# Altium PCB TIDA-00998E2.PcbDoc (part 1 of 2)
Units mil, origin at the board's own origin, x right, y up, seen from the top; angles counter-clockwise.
Board outline 2559.06 x 2559.06 mil, 2 copper layers (Top Layer, Bottom Layer), stack 62 mil thick; 110 components, 76 nets, 294 pads, 121 vias.
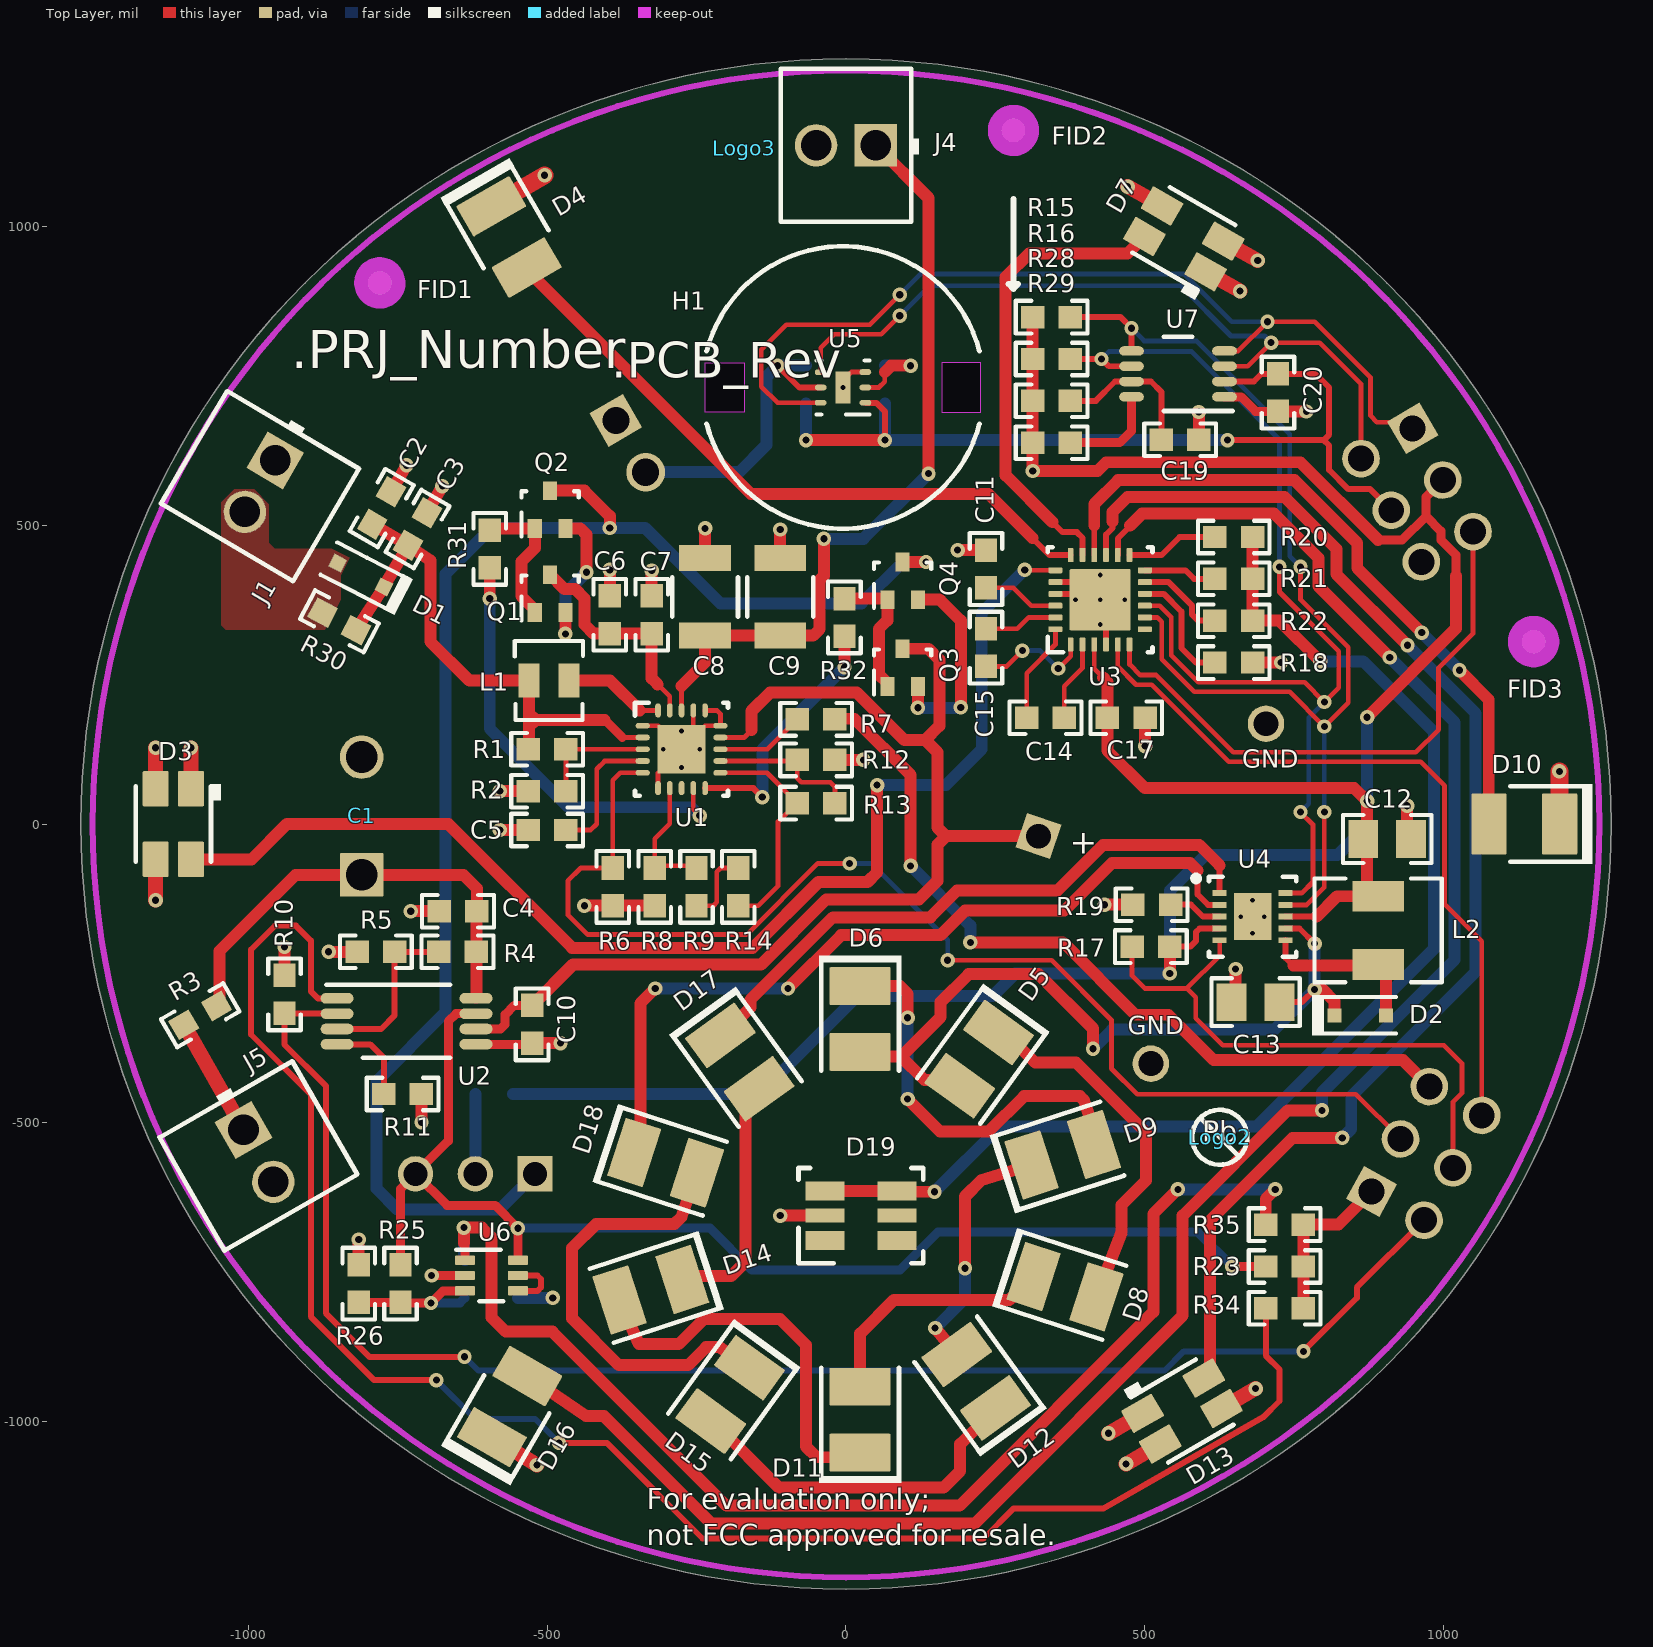
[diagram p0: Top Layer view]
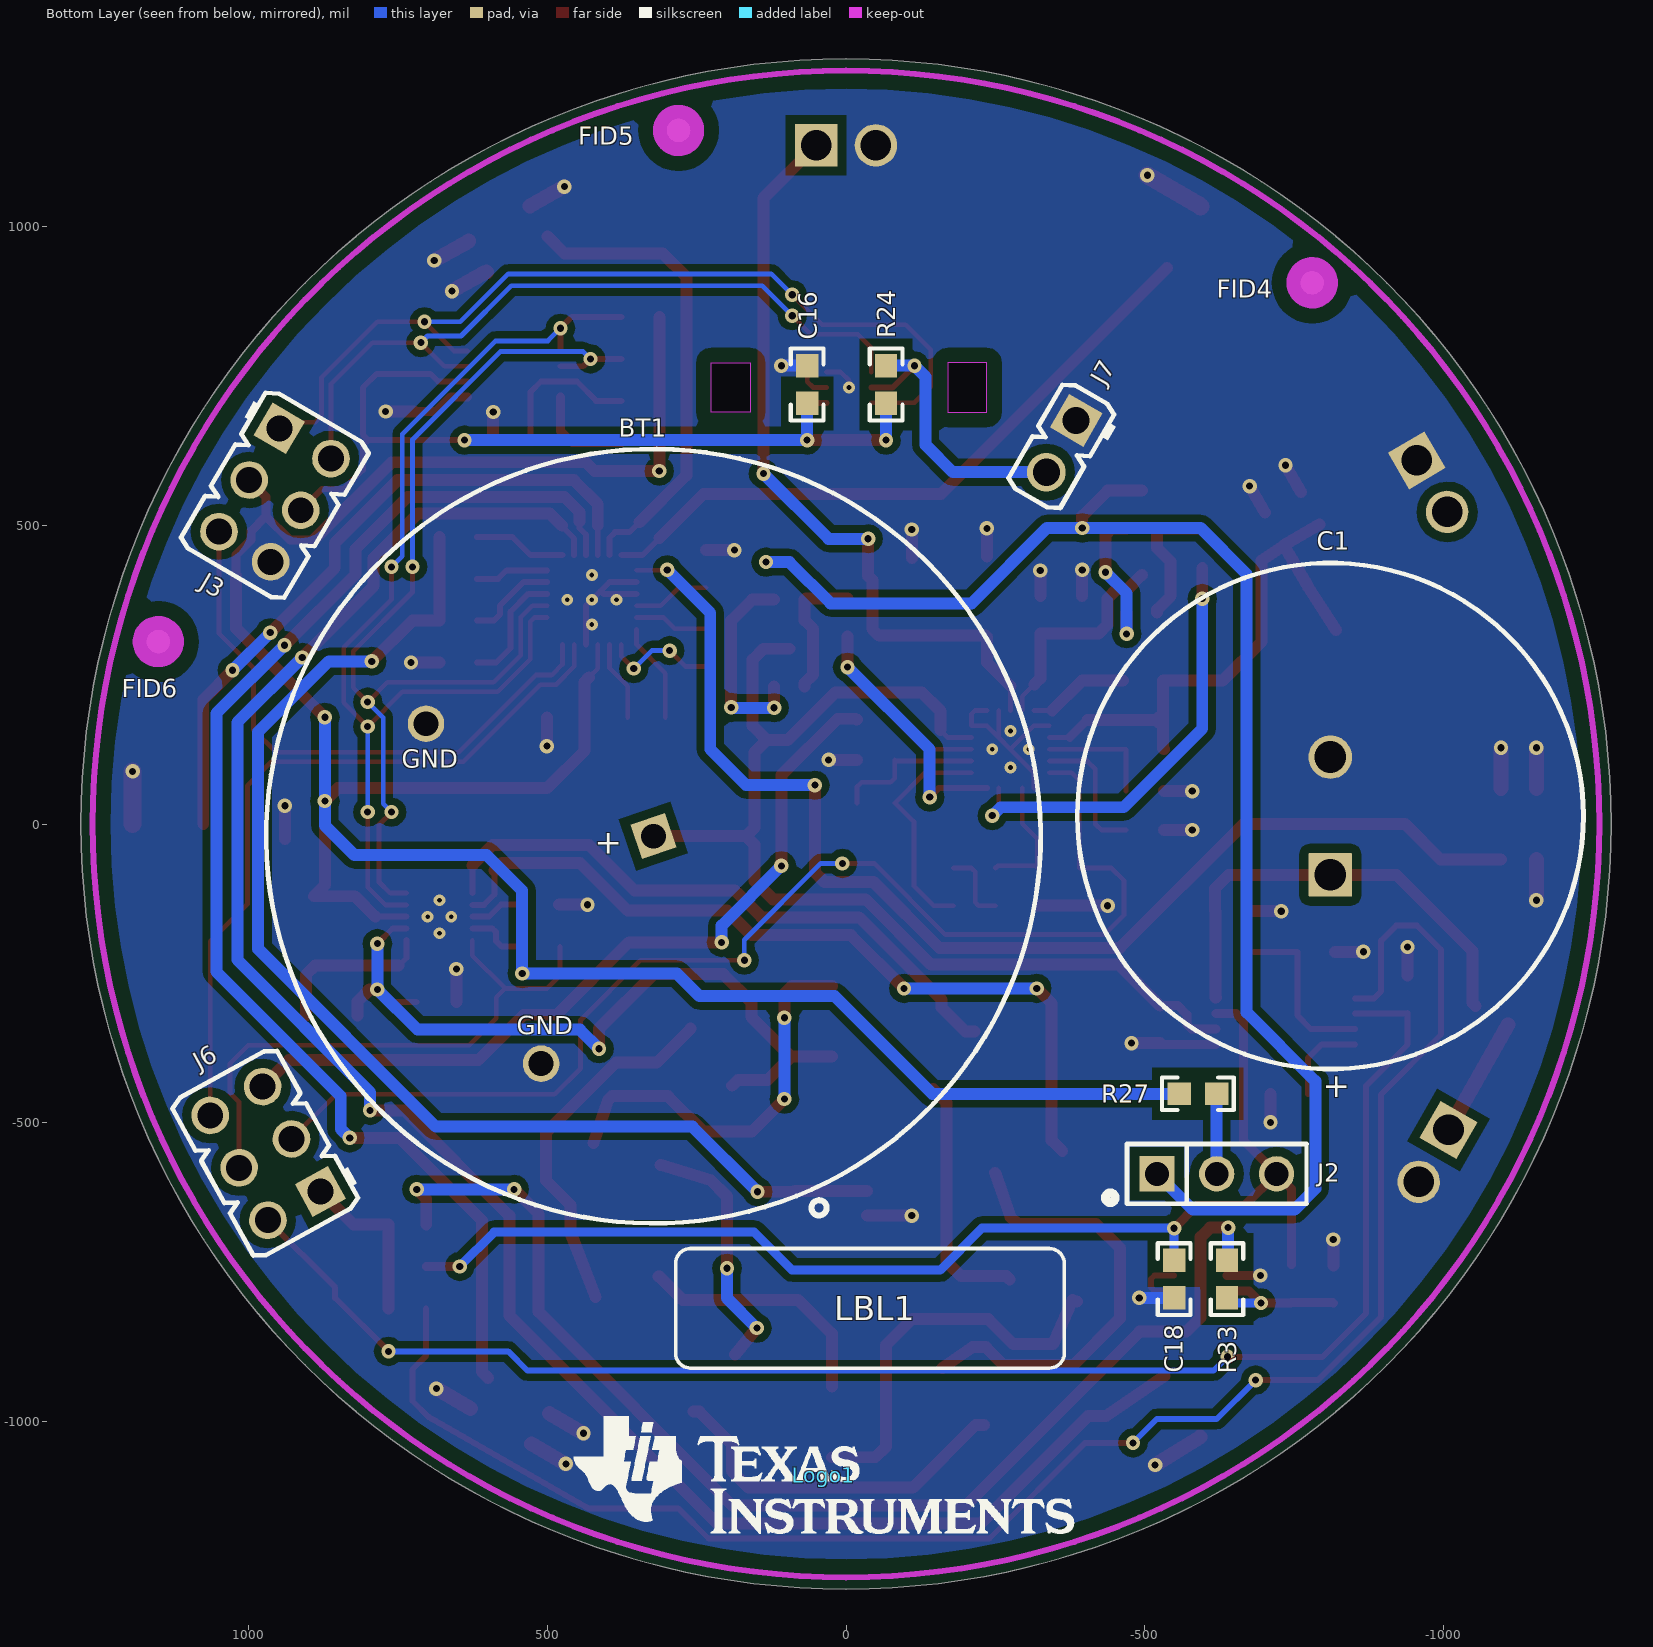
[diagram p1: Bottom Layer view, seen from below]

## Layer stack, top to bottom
Top Solder: solder mask 0.4, Solder Resist, Dk 3.5
Top Layer: signal copper 1.4
Dielectric1: core 59.2, FR-4 High Tg, Dk 4.8
Bottom Layer: signal copper 1.4
Bottom Solder: solder mask 0.4, Solder Resist, Dk 3.5

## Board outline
0,-1279.53 cw(c0,0) -1279.53,0 cw(c0,0) 0,1279.53 cw(c0,0) 1279.53,0 cw(c0,0)

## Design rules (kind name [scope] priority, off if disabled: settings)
AcuteAngle [All] p1: minimum=4.50000000000000E+0001 checktracksonly=FALSE
AssemblyTestPointUsage [All] p1: valid=2
Clearance Clearance_Keepouts [((IsTrack Or IsArc) And Not InPoly) And IsFree and IsKeepOut vs ((IsTrack Or IsArc) And Not InPoly) And IsFree and IsKeepOut] p1: gap=0
Clearance Clearance_Poly [InPolygon] p2: gap=25 except(12: Track-Poly Via-Poly; 15: THPad-Poly)
Clearance [All] p3: gap=7.87 except(8: Track-Track)
ComponentClearance ComponentClearance_MountingHoles_FiducialMarks [InComponentClass('Mounting Holes') vs InComponentClass('FiducialMark')] p1: gap=50 collisioncheckmode=3 verticalgap=10 showdistances=FALSE
ComponentClearance ComponentClearance_Shunt [InComponentClass('Header') vs InComponentClass('Shunt')] p2: gap=0 collisioncheckmode=3 verticalgap=0 showdistances=FALSE
ComponentClearance ComponentClearance_Logo [InComponentClass('Logo')] p3: gap=50 collisioncheckmode=3 verticalgap=10 showdistances=FALSE
ComponentClearance ComponentClearance_ScrewToNut [(HasFootprint('NY PMS 440 0025 PH')) vs (HasFootprint('Keystone_1902C'))] p4: gap=5 collisioncheckmode=3 verticalgap=10 showdistances=FALSE
ComponentClearance ComponentClearance_MountingHoles [InComponentClass('Mounting Holes')] p5: gap=250 collisioncheckmode=3 verticalgap=100000 showdistances=FALSE
ComponentClearance ComponentClearance_SmallPassives [HasFootprint('0201*') or HasFootprint('0402*') or HasFootprint('0508') or HasFootprint('0603*') or HasFootprint('0612') or HasFootprint('0805*') or HasFootprint('0815*') or HasFootprint('0830*') or HasFootprint('1206*') or HasFootprint('1210*') or HasFootprint('1808*') or HasFootprint('1812*') or HasFootprint('1825*') or HasFootprint('2010*') or HasFootprint('2220*') or HasFootprint('2225*') or HasFootprint('2512*') or HasFootprint('2728*') or HasFootprint('3518*') vs HasFootprint('0201*') or HasFootprint('0402*') or HasFootprint('0508') or HasFootprint('0603*') or HasFootprint('0612') or HasFootprint('0805*') or HasFootprint('0815*') or HasFootprint('0830*') or HasFootprint('1206*') or HasFootprint('1210*') or HasFootprint('1808*') or HasFootprint('1812*') or HasFootprint('1825*') or HasFootprint('2010*') or HasFootprint('2220*') or HasFootprint('2225*') or HasFootprint('2512*') or HasFootprint('2728*') or HasFootprint('3518*')] p6: gap=14.96 collisioncheckmode=3 verticalgap=10 showdistances=FALSE
ComponentClearance ComponentClearance_THtoSMT [IsThruComponent vs IsSMTComponent] p7: gap=40 collisioncheckmode=3 verticalgap=30 showdistances=FALSE
ComponentClearance ComponentClearance_THtoTH [IsThruComponent vs IsThruComponent] p8: gap=25 collisioncheckmode=3 verticalgap=30 showdistances=FALSE
ComponentClearance [All] p9: gap=30 collisioncheckmode=3 verticalgap=10 showdistances=FALSE
DiffPairsRouting [All] p1: maxlimit=100 minlimit=10 mostfreqgap=10 toplayer_minwidth=15 toplayer_maxwidth=15 toplayer_prefwidth=15 bottomlayer_minwidth=15 bottomlayer_maxwidth=15 bottomlayer_prefwidth=15 maxuncoupledlength=1000
FabricationTestPointUsage TestPointUsage [All] p1: valid=2 allowmultiple=FALSE
FabricationTestpoint Testpoint [All] p1: side=3 testpointundercomponent=TRUE minsize=40 maxsize=100 preferedsize=60 minholesize=0 maxholesize=40 preferedholesize=32 testpointgrid=1 allowsidetop=TRUE allowsidebottom=TRUE usegrid=TRUE gridtolerance=0.01
FanoutControl Fanout_LCC [IsLCC] p1: bgadir=Out bgaviamode=Centered fanoutstyle=Auto fanoutdirection=Alternating viagrid=1 // Fanout_LCC (Default Rule)
FanoutControl Fanout_BGA [IsBGA] p2: bgadir=Out bgaviamode=Centered fanoutstyle=Auto fanoutdirection=Alternating viagrid=1 // Fanout_BGA (Default Rule)
FanoutControl Fanout_Default [All] p4: bgadir=Out bgaviamode=Centered fanoutstyle=Auto fanoutdirection=Alternating viagrid=1 // Fanout_Default (Default Rule)
FanoutControl Fanout_Small [(CompPinCount < 5)] p5: bgadir=Out bgaviamode=Centered fanoutstyle=Auto fanoutdirection=OutThenIn viagrid=1 // Fanout_Small (Default Rule)
HoleSize [All] p1: absolutevalues=TRUE maxlimit=251 minlimit=7.87 maxpercent=80.000 minpercent=20.000
MinimumAnnularRing MinimumAnnularRing_ThermalPadVias [IsVia and InAnyComponent] p1: minimumring=5.91
MinimumAnnularRing [All] p2: minimumring=6
MinimumSolderMaskSliver MinimumSolderMaskSliver_Logo [InComponentClass('Logo') vs InComponentClass('Logo')] p1: minsoldermaskwidth=0.7
MinimumSolderMaskSliver [All] p2: minsoldermaskwidth=3.94
PlaneConnect [All] p1: planeconnectstyle=Relief reliefexpansion=10 reliefentries=4 reliefconductorwidth=10 reliefairgap=10
PolygonConnect PolygonConnect_Via [IsVia] p1: connectstyle=Direct reliefconductorwidth=10 reliefentries=4 polygonreliefangle="90 Angle" airgapwidth=10
PolygonConnect PolygonConnect_1 [All] p2: connectstyle=Direct reliefconductorwidth=15 reliefentries=4 polygonreliefangle="90 Angle" airgapwidth=10
RoutingVias ThermalPadVias [IsVia and InAnyComponent] p1: holewidth=7.87 width=19.68 viastyle="Through Hole" minholewidth=7.87 minwidth=19.68 maxholewidth=12.99 maxwidth=23.62
RoutingVias [All] p2: holewidth=12 width=24 viastyle="Through Hole" minholewidth=12 minwidth=24 maxholewidth=20 maxwidth=40
SilkToBoardRegionClearance [Not ((IsComment or IsDesignator) And (Hide <> 'False')) and not InRegion(1000,500,4000,800)] p1:
SilkToSilkClearance SilkToSilkClearance_Pb-FreeLogo [(HasFootprint('Pb-Free_Overlay_Medium') OR HasFootprint('Pb-Free_Overlay_Small')) vs (HasFootprint('Pb-Free_Overlay_Medium') OR HasFootprint('Pb-Free_Overlay_Small'))] p1: silktosilkclearance=0
SilkToSilkClearance [All] p2: silktosilkclearance=2
SilkToSolderMaskClearance SilkToComponentPadClearance [IsPad and InAnycomponent] p1: minsilkscreentomaskgap=5 clearancetoexposedcopper=TRUE
SilkToSolderMaskClearance "Silk to Solder Mask Opening" [All] p2: minsilkscreentomaskgap=4 clearancetoexposedcopper=FALSE
SolderMaskExpansion [All] p1: expansion=2
Width [All] p1: maxlimit=100 minlimit=6 preferedwidth=8 checkconnectedcopper=TRUE
15 further rules are at their usual default settings.

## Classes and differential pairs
component class Header: J2 J3 J6 J7
component class TIDA-00998E2_EVM_Hardware: FID1 FID2 FID3 FID4 FID5 FID6 H1 LBL1 Logo1 Logo2 Logo3 ZZ1 ZZ2 ZZ3 ZZ4
component class FiducialMark: FID1 FID2 FID3 FID4 FID5 FID6
component class AssemblyNote: ZZ1 ZZ2 ZZ3 ZZ4
component class Label: LBL1
component class Logo: Logo1
component class TIDA-00998E2_BlankSheet: BT1 C1 C2 C3 C4 C5 C6 C7 C8 C9 C10 C11 C12 C13 C14 C15 C16 C17 C18 C19 C20 D1 D2 D3 D4 D5 D6 D7 D8 D9 D10 D11 D12 D13 D14 D15 D16 D17 D18 D19 J1 J2 J3 J4 J5 J6 J7 L1 L2 Q1 Q2 Q3 Q4 R1 R2 R3 R4 R5 R6 R7 R8 R9 R10 R11 R12 R13 R14 R15 R16 R17 R18 R19 R20 R21 R22 R23 R24 R25 R26 R27 R28 R29 R30 R31 R32 R33 R34 R35 U1 U2 U3 U4 U5 U6 U7

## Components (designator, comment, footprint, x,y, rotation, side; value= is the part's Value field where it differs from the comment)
BT1 "TL-4934/P" Tadiran_TL-4934 322.04,-20.32 r251.3 bottom locked
C1 "DB-5R5D105T" DB_2150x800 -810,13.43 r90 top locked
C2 "0603ZD475KAT2A" 0603 -776.56,528.32 r60 top
C3 "06033C104JAT2A" 0603 -716.56,493.32 r60 top
C4 "06033C104JAT2A" 0603 -648.91,-145.8 r180 top
C5 "C0603C103J5RACTU" 0603 -500,-10 r180 top
C6 "0603ZD475KAT2A" 0603 -395,350 r90 top
C7 "06033C104JAT2A" 0603 -325,350 r90 top
C8 "C1210C107M8PACTU" 1210_280 -235.63,380 r90 top
C9 "C1210C107M8PACTU" 1210_280 -110,380 r90 top
C10 "06033C104JAT2A" 0603 -525,-335 r270 top
C11 "C0603C105K8PACTU" 0603 234.14,426.48 r90 top
C12 "GRM219R61E225KA12D" 0805_HV 905,-25 r180 top
C13 "GRM219R61E225KA12D" 0805_HV 685,-297.94 r0 top
C14 "C0603C474K8PACTU" 0603 333.68,177.8 r180 top
C15 "C0603C474K8PACTU" 0603 234.14,294.98 r90 top
C16 "06033C104JAT2A" 0603 65,735 r90 bottom
C17 "06033C104JAT2A" 0603 468.68,177.73 r0 top
C18 "06033C104JAT2A" 0603 -548.68,-761 r270 bottom
C19 "06033C104JAT2A" 0603 558.76,642.75 r0 top
C20 "06033C104JAT2A" 0603 722.5,721.45 r270 top
D1 "1SS315TPH3F" SOD-323 -811.4,416.43 r152.75 top
D2 "1N4448WX-TP" SOD-323 860,-320 r0 top
D3 "HSMZ-A400-V30M1" HSMx-A4xx_Red -1125,0 r180 top
D4 "VAOL-S2WR4" VAOL-S2WR4_Yellow -563.64,981.86 r120 top
D5 "VLMR334BACB-GS08" VLMR334_Red#1 222.69,-393.19 r54 top
D6 "VLMR334BACB-GS08" VLMR334_Red#1 23.59,-326.06 r90 top
D7 "HSMZ-A400-V30M1" HSMx-A4xx_Red 565,978.61 r60 top
D8 "VLMR334BACB-GS08" VLMR334_Red#1 366.26,-773.78 r162 top
D9 "VLMR334BACB-GS08" VLMR334_Red#1 362.42,-552.97 r198 top
D10 "VAOL-S2WR4" VAOL-S2WR4_Yellow 1134.49,0 r0 top
D11 "VLMR334BACB-GS08" VLMR334_Red#1 23.59,-996.06 r270 top
D12 "VLMR334BACB-GS08" VLMR334_Red#2 137.51,-921.94 r126 top
D13 "HSMZ-A400-V30M1" HSMx-A4xx_Red 562.03,-981.64 r300 top
D14 "VLMR334BACB-GS08" VLMR334_Red#1 -326.26,-778.78 r18 top
D15 "VLMR334BACB-GS08" VLMR334_Red#3 -189.2,-947.56 r54 top
D16 "VAOL-S2WR4" VAOL-S2WR4_Yellow -562.5,-974.28 r240 top
D17 "VLMR334BACB-GS08" VLMR334_Red#1 -177.69,-398.19 r126 top
D18 "VLMR334BACB-GS08" VLMR334_Red#1 -301.77,-566.22 r162 top
D19 "LNJ8L6C18RA" LNJ8L6C18RA_Red 25,-655 r90 top
FID1 "Fiducial" Fiducial10-20 -779.68,905 r20.33 top
FID2 "Fiducial" Fiducial10-20 280,1160 r0 top
FID3 "Fiducial" Fiducial10-20 1150,305 r169.88 top
FID4 "Fiducial" Fiducial10-20 -779.68,905 r90 bottom
FID5 "Fiducial" Fiducial10-20 280,1160 r90 bottom
FID6 "Fiducial" Fiducial10-20 1150,305 r90 bottom
H1 "IML-0669" Murata_IML-0669 -5,730 r0 top locked
J1 "OSTVN02A150" On-Shore_OSTVN02A150 -980,565 r239.51 top
J2 "PEC03SAAN" CONN_PEC03SAAN -620,-585 r180 bottom
J3 "61300621121" Wurth_61300621121 955,550 r210.31 bottom
J4 "OSTVN02A150" On-Shore_OSTVN02A150 0,1135 r180 top
J5 "OSTVN02A150" On-Shore_OSTVN02A150 -982.75,-555 r299.86 top
J6 "61300621121" Wurth_61300621121 971.2,-550.88 r331.15 bottom
J7 "61300211121" WURTH_61300211121 -360,631.6 r300 bottom
L1 "VLF302515MT-100M" VLF302515MT -496.79,240 r0 top
L2 "VLF504012MT-100M" VLF504012MT 890,-177.91 r270 top
LBL1 "Size: 0.65\" x 0.20 \"" Label_650x200 -40,-810 r180 bottom
Logo1 "Texas Instruments" TI_Stacked_Overlay_Small 37,-1089 r180 bottom
Logo2 "Pb-Free Symbol" Pb-Free_Overlay_Small 625,-524 r0 top
Logo3 "FCC disclaimer" FCC_disclaimer -170,1130 r0 top
Q1 "SI1317DL-T1-GE3" SOT-323 -494.88,385.27 r90 top
Q2 "SI1317DL-T1-GE3" SOT-323 -494.88,525.93 r90 top
Q3 "SI1317DL-T1-GE3" SOT-323 94.68,261.57 r90 top
Q4 "SI1317DL-T1-GE3" SOT-323 94.68,406.57 r90 top
R1 "RC0603JR-070RL" 0603 -500,125 r0 top
R2 "CRCW0603100KFKEA" 0603 -500,55 r180 top
R3 "RC0603JR-070RL" 0603 -1080,-320 r30 top
R4 "CRCW06033M48FKEA" 0603 -649.7,-213.74 r0 top
R5 "CRCW06031M00FKEA" 0603 -786.2,-213.74 r0 top
R6 "RC0603JR-070RL" 0603 -390,-105.08 r90 top
R7 "RC0603JR-070RL" 0603 -50,175 r180 top
R8 "CRCW06035M49FKEA" 0603 -320,-105.08 r90 top
R9 "CRCW06037M32FKEA" 0603 -250,-105.08 r270 top
R10 "RC0603JR-070RL" 0603 -939.05,-284.8 r270 top
R11 "CRCW0603499RFKEA" 0603 -741.5,-451.56 r180 top
R12 "CRCW06034M32FKEA" 0603 -50,107.24 r180 top
R13 "CRCW06037M50FKEA" 0603 -50,35 r180 top
R14 "CRCW06031M18FKEA" 0603 -180,-105.08 r90 top
R15 "CRCW060310K0FKEA" 0603 343.76,847.75 r180 top
R16 "CRCW060310K0FKEA" 0603 343.76,777.75 r180 top
R17 "CRCW060310K0FKEA" 0603 510,-205 r0 top
R18 "RC0603JR-070RL" 0603 648.5,270 r180 top
R19 "CRCW06038K06FKEA" 0603 511.26,-135 r0 top
R20 "RC0603JR-070RL" 0603 648.5,480 r0 top
R21 "RC0603JR-070RL" 0603 648.5,410 r0 top
R22 "RC0603JR-070RL" 0603 648.5,340 r0 top
R23 "CRCW060310K0FKEA" 0603 733.5,-740 r180 top
R24 "CRCW060310K0FKEA" 0603 -67,735 r270 bottom
R25 "CRCW06031M80FKEA" 0603 -745,-768.5 r90 top
R26 "CRCW06031M00FKEA" 0603 -815,-768.5 r270 top
R27 "RC0603JR-070RL" 0603 -588.5,-451.31 r180 bottom
R28 "RC0603FR-07200KL" 0603 343.76,707.75 r180 top
R29 "RC0603FR-07200KL" 0603 343.76,637.75 r180 top
R30 "RC0603JR-070RL" 0603 -847.3,338.95 r332.38 top
R31 "RC0603JR-070RL" 0603 -595.78,460 r90 top
R32 "RC0603JR-070RL" 0603 -2.59,345.41 r90 top
R33 "CRCW060352K3FKEA" 0603 -637.27,-761 r90 bottom
R34 "RC0603JR-070RL" 0603 733.5,-810 r0 top
R35 "RC0603JR-070RL" 0603 733.5,-670 r0 top
U1 "BQ25505RGRR" RGR0020A -275,125 r0 top
U2 "TPS2113APWR" PW0008A_N -735,-330 r0 top
U3 "LP55231SQX/NOPB" RTW0024A 425,375 r90 top
U4 "LM3509SD/NOPB" SDA10A 680,-155 r0 top
U5 "OPT3001DNPR" DNP0006A -5,730 r180 top
U6 "TLV3011AIDCKR" DCK0006A_N -592.97,-755.09 r0 top
U7 "PCA9306DCTR" DCT0008A_N 555.26,752.75 r180 top
ZZ1 "This Assembly Note is for PCB labels only" AssemblyNoteLabel -1857,1881 r0 top
ZZ2 "These assemblies are ESD sensitive, ESD precautions shall be observed." AssemblyNote -1857,1772.11 r0 top
ZZ3 "These assemblies must be clean and free from flux and all contaminants. Use of no clean flux is not acceptable." AssemblyNote -1857,1683.56 r0 top
ZZ4 "These assemblies must comply with workmanship standards IPC-A-610 Class 2, unless otherwise specified." AssemblyNote -1857,1595 r0 top

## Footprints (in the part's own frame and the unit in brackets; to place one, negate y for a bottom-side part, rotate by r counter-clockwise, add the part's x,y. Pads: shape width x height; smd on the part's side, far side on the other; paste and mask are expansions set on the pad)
0603 [mm] "0603 from SM-752 data"
  rect 1x0.95 smd: 1(-0.8,0) 2(0.8,0)
  silkscreen extent -1.52,-0.69 1.52,0.69, body extent -0.87,-0.47 0.87,0.47, height 1
0805_HV [mil] "0805 with 30mil clearance between pads"
  rect 50x63 smd: 1(-40,0) 2(40,0)
  silkscreen extent -74,-40 74,40, body extent -43,-29 43,29, height 57
1210_280 [mm] "SMD, 2-Leads, Body 3.6x2.8mm, Height 2.8mm"
  rect 1.1x2.2 smd: 1(-1.65,0) 2(1.65,0)
  silkscreen extent -0.84,-1.4 0.84,1.4, body extent -1.8,-1.4 1.8,1.4, height 2.8
AssemblyNote [mil] "Assembly Note"
AssemblyNoteLabel [mil] "Assembly Note for PCB Labels"
CONN_PEC03SAAN [mm] "SULLINS"
  rect 1.5x1.5 hole 1.016: 1(-2.54,0)
  round 1.5 hole 1.016: 2(0,0) 3(2.54,0)
  silkscreen extent -4.72,-1.27 3.81,1.27, body extent -3.84,-1.3 3.84,1.3, height 8.38
DB_2150x800 [mm] "TH, 2-Leads, Dia 21.5mm, Pin Spacing 5mm"
  rrect5% 1.85x1.85 hole 1.35: 1(-2.5,0)
  round 1.85 hole 1.35: 2(2.5,0)
  body extent -10.75,-10.75 10.76,10.75, height 12.51
DCK0006A_N [mm] "SOT23, 6-Leads, Body 2x1.3mm, Pitch 0.65mm, Lead Span 2.1mm, IPC Medium Density"
  rrect25% 0.85x0.4 smd: 1(-1.125,0.65) 2(-1.125,0) 3(-1.125,-0.65) 4(1.125,-0.65) 5(1.125,0) 6(1.125,0.65)
  silkscreen extent -1.5,-1.09 0.51,1.09, body extent -1.14,-1 1.14,1, height 0.95
DCT0008A_N [mm] "TSOP, 8-Leads, Body 3x2.8mm, Pitch 0.65mm, IPC Medium Density"
  oval 1.05x0.4 smd: 1(-1.975,0.975) 2(-1.975,0.325) 3(-1.975,-0.325) 4(-1.975,-0.975) 5(1.975,-0.975) 6(1.975,-0.325) 7(1.975,0.325) 8(1.975,0.975)
  silkscreen extent -2.32,-1.57 0.6,1.58, body extent -2.01,-1.47 2.01,1.48, height 1.3
DNP0006A [mm] "DFN-6 2x2mm"
  oval 0.5x0.25 smd: 1(-0.95,0.65) 2(-0.95,0) 3(-0.95,-0.655) 4(0.95,-0.65) 5(0.95,0) 6(0.95,0.65)
  rect 0.65x1.35 smd paste-0.5: 7(0,0)
  silkscreen extent -1.12,-1.15 1.12,1.15, body extent -1,-1 1,1, height 0.64
FCC_disclaimer [mil]
Fiducial10-20 [mm]
  round 1 smd mask+0.5: 1(0,0)
  Top Layer keep-out lines w1.178: 0.5,0.006 ccw(c0,0) 0.5,0.006
HSMx-A4xx_Red [mm] "SMD, 4-Leads, Body 3.2x2.8mm"
  rrect9% 1.1x1.5 smd: 1(-0.75,1.5) 2(-0.75,-1.5) 2(0.75,1.5) 2(0.75,-1.5)
  silkscreen extent -2.03,-1.7 1.6,1.6, body extent -1.5,-1.85 1.5,1.85, height 2.1
Label_650x200 [mil] "Thermal Transfer Label"
  silkscreen extent -325,-100 325,100, body extent -325,-100 325,100, height 1
LNJ8L6C18RA_Red [mm] "SMT, 6-Leads, Body 3.3x3.1mm, Pitch 1.05mm"
  rect 0.8x1.65 smd: 1(-1.05,1.525) 3(1.05,1.525) 4(1.05,-1.525) 6(-1.05,-1.525)
  rect 0.6x1.65 smd: 2(0,1.525) 5(0,-1.525)
  silkscreen extent -2.03,-2.65 2.03,2.65, body extent -1.73,-1.82 1.72,1.83, height 1.95
Murata_IML-0669 [mil] "Pyroelectric Infrared Lens, TH"
  Keep-Out Layer board cut-out: -165.35,-41.34 -230.32,-41.34 -230.32,41.34 -165.35,41.34
  Keep-Out Layer board cut-out: 165.35,-41.34 230.32,-41.34 230.32,41.34 165.35,41.34
  silkscreen extent -228,-236 228,236, body extent -256,-236 256,236, height 335
On-Shore_OSTVN02A150 [mm] "Terminal Block, 2.54mm, 2-pole, Brass, TH"
  rect 1.8x1.8 hole 1.3: 1(-1.27,0)
  round 1.8 hole 1.3: 2(1.27,0)
  silkscreen extent -3.1,-3.25 2.77,3.25, body extent -2.77,-3.25 2.77,3.25, height 8.51
Pb-Free_Overlay_Small [mil]
  silkscreen extent -46,-46 46,46
PW0008A_N [mm] "TSOP, 8-Leads, Body 3x4.4mm, Pitch 0.65mm, IPC Medium Density"
  oval 1.4x0.45 smd: 1(-2.95,0.975) 2(-2.95,0.325) 3(-2.95,-0.325) 4(-2.95,-0.975) 5(2.95,-0.975) 6(2.95,-0.325) 7(2.95,0.325) 8(2.95,0.975)
  silkscreen extent -3.4,-1.55 1.85,1.55, body extent -3.21,-1.5 3.21,1.5, height 1.2
RGR0020A [mm] "QFN, 20-Leads, Body 3.5x3.5mm, Pitch 0.5mm, Thermal Pad 2.05x2.05mm, TI Recommended"
  oval 0.6x0.24 smd: 1(-1.65,1) 2(-1.65,0.5) 3(-1.65,0) 4(-1.65,-0.5) 5(-1.65,-1) 11(1.65,-1) 12(1.65,-0.5) 13(1.65,0) 14(1.65,0.5) 15(1.65,1)
  oval 0.24x0.6 smd: 6(-1,-1.65) 7(-0.5,-1.65) 8(0,-1.65) 9(0.5,-1.65) 10(1,-1.65) 16(1,1.65) 17(0.5,1.65) 18(0,1.65) 19(-0.5,1.65) 20(-1,1.65)
  rect 2.05x2.05 smd paste-1.025: 21(0,0)
  silkscreen extent -1.97,-1.97 1.97,1.97, body extent -1.83,-1.83 1.83,1.83, height 1.01
RTW0024A [mm] "QFN, 24-Leads, Body 4x4mm, Pitch 0.5mm, Thermal Pad 2.6x2.6mm, TI Recommended"
  rrect40% 0.6x0.25 smd: 1(-1.9,1.25) 2(-1.9,0.75) 3(-1.9,0.25) 4(-1.9,-0.25) 5(-1.9,-0.75) 6(-1.9,-1.25) 13(1.9,-1.25) 14(1.9,-0.75) 15(1.9,-0.25) 16(1.9,0.25) 17(1.9,0.75) 18(1.9,1.25)
  rrect40% 0.25x0.6 smd: 7(-1.25,-1.9) 8(-0.75,-1.9) 9(-0.25,-1.9) 10(0.25,-1.9) 11(0.75,-1.9) 12(1.25,-1.9) 19(1.25,1.9) 20(0.75,1.9) 21(0.25,1.9) 22(-0.25,1.9) 23(-0.75,1.9) 24(-1.25,1.9)
  rrect4% 2.6x2.6 smd paste-1.3: 25(0,0)
  silkscreen extent -2.22,-2.22 2.22,2.22, body extent -2,-2 2,2, height 0.8
SDA10A [mm] "SON, 10-Leads, Body 3x3 mm, Pitch 0.5mm, NSC Recommended"
  rect 0.6x0.25 smd paste-0.125 mask+0.051: 1(-1.4,1) 2(-1.4,0.5) 3(-1.4,0) 4(-1.4,-0.5) 5(-1.4,-1) 6(1.4,-1) 7(1.4,-0.5) 8(1.4,0) 9(1.4,0.5) 10(1.4,1)
  rect 1.6x2 smd paste-0.05 mask+0.051: 11(0,0)
  silkscreen extent -2.52,-1.7 1.85,1.75, body extent -1.55,-1.55 1.55,1.55, height 0.8
SOD-323 [mm] "NXP recommended land pattern"
  rect 0.6x0.6 smd paste-0.05: 1(-1.1,0) 2(1.1,0)
  silkscreen extent -2.06,-0.86 1.53,0.86, body extent -1.3,-0.67 1.3,0.68, height 1.1
SOT-323 [mm] "Zetex recommended land pattern.  March 2007"
  rect 0.8x0.6 smd: 1(-0.8,0.65) 2(-0.8,-0.65) 3(0.8,0)
  silkscreen extent -1.14,-1.22 0.77,1.22, body extent -1.13,-1.13 1.12,1.12, height 1.13
Tadiran_TL-4934 [mm] "TH, 3-Leads, Dia 32.9mm"
  rect 1.55x1.55 hole 1.05: 1(0,0)
  round 1.55 hole 1.05: 2(-7.62,-7.62) 2(7.62,-7.62)
  silkscreen extent -16.45,-16.45 16.45,16.45, body extent -16.45,-16.45 16.45,16.45, height 7.2
TI_Stacked_Overlay_Small [mil]
  silkscreen extent -418,-98 418,98
VAOL-S2WR4_Yellow [mm] "SMD, 2-Leads, Body 3.1x2.7mm"
  rrect7% 1.5x2.6 smd: 1(-1.5,0) 2(1.5,0)
  silkscreen extent -0.6,-1.7 2.9,1.7, body extent -1.85,-1.45 1.85,1.45, height 2.1
VLF302515MT [mm] "TDK"
  rect 0.9x1.45 smd: 1(-0.85,0) 2(0.85,0)
  silkscreen extent -1.45,-1.68 1.45,1.68, body extent -1.35,-1.6 1.35,1.6, height 1.5
VLF504012MT [mm] "TDK"
  rect 1.3x2.2 smd: 1(-1.45,0) 2(1.45,0)
  silkscreen extent -2.2,-2.7 2.2,2.7, body extent -2.15,-2.65 2.15,2.65, height 1.2
VLMR334_Red#1 [mm] "SMD, 2-Leads, Body 3x2.8mm"
  rrect6% 1.6x2.6 smd: 1(-1.4,0) 2(1.4,0)
  silkscreen extent -2.2,-1.75 2.7,1.75, body extent -1.75,-1.4 1.75,1.4, height 1.65
VLMR334_Red#2 [mm] "SMD, 2-Leads, Body 3x2.8mm"
  rrect6% 1.6x2.6 smd: 1(0,-1.5) 2(-2.8,-1.5)
  silkscreen extent -4.1,-3.25 0.8,0.25, body extent -3.15,-2.9 0.35,-0.1, height 1.65
VLMR334_Red#3 [mm] "SMD, 2-Leads, Body 3x2.8mm"
  rrect6% 1.6x2.6 smd: 1(-1.6,0) 2(1.2,0)
  silkscreen extent -2.4,-1.75 2.5,1.75, body extent -1.95,-1.4 1.55,1.4, height 1.65
WURTH_61300211121 [mm] "Header, 2.54mm, 2x1, TH"
  rect 1.65x1.65 hole 1.15: 1(-1.27,0)
  round 1.65 hole 1.15: 2(1.27,0)
  silkscreen extent -2.54,-1.27 2.54,1.6, body extent -2.54,-1.27 2.54,1.27, height 8.54
Wurth_61300621121 [mm] "Header, 2.54mm, 3x2, TH"
  rect 1.6x1.6 hole 1.1: 1(-1.27,2.54)
  round 1.6 hole 1.1: 2(1.27,2.54) 3(-1.27,0) 4(1.27,0) 5(-1.27,-2.54) 6(1.27,-2.54)
  silkscreen extent -2.8,-3.82 2.54,3.8, body extent -2.54,-3.82 2.54,3.8, height 7.27

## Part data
BT1: "Battery 3.6V, TH"
C1: "CAP, Electric Double Layer, 1F, 5.5 V, +80/-20%, 30 ohm, TH"
C2 C6: "CAP, CERM, 4.7 µF, 10 V, +/- 10%, X5R, 0603"
C3 C4 C7 C10 C16 C17 C18 C19 C20: "CAP, CERM, 0.1 µF, 25 V, +/- 5%, X7R, 0603"
C5: "CAP, CERM, 0.01 µF, 50 V, +/- 5%, X7R, 0603"
C8 C9: "CAP, CERM, 100 µF, 10 V, +/- 20%, X5R, 1210"
C11: "CAP, CERM, 1 µF, 10 V, +/- 10%, X5R, 0603"
C12 C13: "CAP, CERM, 2.2 µF, 25 V, +/- 10%, X5R, 0805"
C14 C15: "CAP, CERM, 0.47 µF, 10 V, +/- 10%, X5R, 0603"
D1: "Diode, Schottky, 5 V, 0.03 A, SOD-323"
D2: "Diode, Switching, 75 V, 0.25 A, SOD-323"
D3 D5 D6 D7 D8 D9 D11 D12 D13 D14 D15 D17 D18 D19: "LED, Red, SMD"
D4 D10 D16: "LED, Yellow, SMD"
FID1 FID2 FID3 FID4 FID5 FID6: "Fiducial mark.  There is nothing to buy or mount."
H1: "Lens, Ceiling Mount, TH"
J1 J4 J5: "Terminal Block, 2.54mm, 2x1, Brass, TH"
J2: "Header, 100mil, 3x1, Tin, TH"
J3 J6: "Header, 2.54mm, 3x2, Gold, TH"
J7: "Header, 2.54 mm, 2x1, Gold, TH"
L1: "Inductor, Shielded, Ferrite, 10 µH, 0.71 A, 0.152 ohm, SMD"
L2: "Inductor, Shielded, Ferrite, 10 µH, 1.3 A, 0.19 ohm, SMD"
LBL1: library part THT-14-423-10, "Thermal Transfer Printable Labels, 0.650\" W x 0.200\" H - 10,000 per roll"
Logo1: library part TI_Logo, "Texas Instrument Corporate Signature"
Logo2: library part Pb-Free
Logo3: library part FCC_disclaimer, "FCC_disclaimer"
Q1 Q2 Q3 Q4: "MOSFET, P-CH, -20 V, -1.4 A, SOT-323"
R1 R3 R6 R7 R10 R18 R20 R21 R22 R27 R30 R31 R32 R34 R35: "RES, 0, 5%, 0.1 W, 0603"
R2: "RES, 100 k, 1%, 0.1 W, 0603"
R4: "RES, 3.48 M, 1%, 0.1 W, 0603"
R5 R26: "RES, 1.00 M, 1%, 0.1 W, 0603"
R8: "RES, 5.49 M, 1%, 0.1 W, 0603"
R9: "RES, 7.32 M, 1%, 0.1 W, 0603"
R11: "RES, 499, 1%, 0.1 W, 0603"
R12: "RES, 4.32 M, 1%, 0.1 W, 0603"
R13: "RES, 7.50 M, 1%, 0.1 W, 0603"
R14: "RES, 1.18 M, 1%, 0.1 W, 0603"
R15 R16 R17 R23 R24: "RES, 10.0 k, 1%, 0.1 W, 0603"
R19: "RES, 8.06 k, 1%, 0.1 W, 0603"
R25: "RES, 1.80 M, 1%, 0.1 W, AEC-Q200 Grade 0, 0603"
R28 R29: "RES, 200 k, 1%, 0.1 W, 0603"
R33: "RES, 52.3 k, 1%, 0.1 W, 0603"
U1: "Ultra Low Power Boost Converter with Battery Management for Energy Harvester Applications, RGR0020A (VQFN-20)"
U2: "AUTOSWITCHING POWER MUX, PW0008A (TSSOP-8)"
U3: "LP55231 Programmable 9-Output LED Driver, RTW0024A (WQFN-24)"
U4: "High Efficiency Boost for White LED's and/or OLED Displays with Dual Current Sinks and IC Compatible Brightness Control, 10-pin LLP, Pb-Free"
U5: "Ambient Light Sensor, DNP0006A (USON-6)"
U6: "Nanopower, 1.8V, Comparator with Voltage Reference, DCK0006A (SOT-6)"
U7: "Dual Bi-Directional I2C-Bus and SMBus Voltage Level-Translator, 0 to 5.5 V, -40 to 85 degC, 8-pin SM8 (DCT), Green (RoHS & no Sb/Br)"
ZZ1: library part AssemblyNoteLabel
ZZ2 ZZ3 ZZ4: library part AssemblyNote

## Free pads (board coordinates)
  rect 0x0 hole 65 square unplated mask+5: 2(-202.83,730) 2(193,730)

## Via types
v1: diameter 24, hole 12, Top Layer to Bottom Layer, tented both sides, 107 vias
v2: diameter 19.68, hole 7.87, Top Layer to Bottom Layer, 10 vias
v3: diameter 19.68, hole 7.87, Top Layer to Bottom Layer, tented top, 4 vias

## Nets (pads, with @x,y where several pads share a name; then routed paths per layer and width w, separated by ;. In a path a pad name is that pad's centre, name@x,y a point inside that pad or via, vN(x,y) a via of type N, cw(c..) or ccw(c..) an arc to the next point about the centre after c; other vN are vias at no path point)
/EN_BQ: J6.3 R6.2 U1.5 | length 2056.3
  Top Layer w8: U1.5@-339.96,85.63 -377.37,85.63 -390,73 R6.2@-390,-73.58 -443.58,-73.58 -465,-95 -465,-152 -432,-185 -166,-185 -47,-66 v1(6,-66) ; v1(170,-228) 344,-228 444,-328 444,-409 487,-452 852.65,-452 J6.3@927.41,-526.75
  Bottom Layer w8: v1(6,-66) 42,-66 170,-194 v1(170,-228)
/EN_PMUX: J6.2 R10.2 U2.2 | length 2609.6
  Top Layer w10: U2.2@-851.14,-317.2 -938.14,-317.2 R10.2@-939.05,-316.3 -939.05,-368.95 -870,-438 -870,-818 -797,-891 v1(-638,-891) ; v1(765,-882) 854.35,-792.65 854.35,-775 J6.2@966.75,-662.59
  Bottom Layer w10: v1(-638,-891) -615,-914 533,-914 565,-882 v1(765,-882)
BQ_VBAT_OK: J6.5 R7.1 | length 1354.8
  Top Layer w20: R7.1@-18.5,175 -17.28,175 -16.28,176 14,176 108,82 v1(108,-70) ; v1(208,-198) 363,-198 484,-319 539,-319 615,-395 931.49,-395 J6.5@975.65,-439.16
  Bottom Layer w20: v1(108,-70) 208,-170 v1(208,-198)
CLK: J3.5 U3.6 | length 981.5
  Top Layer w8: U3.6@474.21,300.2 474.21,266.79 492,249 519,249 648,120 953,120 991,158 991,261 1048.63,318.63 J3.5@1048.63,488.9
CT_I/P: J5.1 R3.1 | length 202.1
  Top Layer w25: R3.1@-1107.28,-335.75 J5.1@-1007.64,-511.64
D1: D3.1 U3.19 | length 2037.1
  Top Layer w8: v1(299,425) 299.79,424.21 U3.19@350.2,424.21
  Top Layer w20: D3.1@-1095.47,-59.06 -994.06,-59.06 -935,0 -665,0 -458,-207 -156,-207 -46,-97 36,-97 52,-81 v1(52,65)
  Bottom Layer w20: v1(52,65) 167,65 227,125 227,353 v1(299,425)
D2: D4.1 U3.18 | length 1111.3
  Top Layer w10: 312,478 340.2,449.8 U3.18@375.79,449.8
  Top Layer w20: D4.1@-536.72,929.63 -159.09,552 238,552 312,478
D3: D7.1 U3.17 | length 792.5
  Top Layer w10: 345,505 362,488 386,488 395.47,478.53 U3.17@395.47,449.8
  Top Layer w20: 345,505 267,583 267,915 306,954 470.53,954 D7.1@499.09,982.56
D4: D10.1 U3.16 | length 1146.3
  Top Layer w10: U3.16@415.16,449.8 415.16,498.84
  Top Layer w20: 415.16,498.84 415.16,535.16 455,575 750,575 855,470 855,428 v1(963,320) ; v1(1026,257) 1074.94,208.06 D10.1@1074.94,0
  Bottom Layer w20: v1(963,320) v1(1026,257)
D5: D13.1 U3.15 | length 2217.2
  Top Layer w10: U3.15@434.84,449.8 434.84,483.84 446,495 446,506
  Top Layer w20: 446,506 446,522 471,547 733,547 820,460 820,418 v1(939,299) ; D13.1@598.41,-926.54 609,-915.95 609,-663 747,-525 v1(830,-525)
  Bottom Layer w20: v1(830,-525) 845,-510 845,-455 1053,-247 1053,185 v1(939,299)
D6: D16.1 U3.14 | length 3330.2
  Top Layer w10: U3.14@454.53,449.8 454.53,477.53 475,498 475,499
  Top Layer w20: D16.1@-532.97,-923.14 -435,-990 -405,-990 -225,-1170 215,-1170 563,-822 563,-655 739,-479 v1(796,-479) ; 475,499 495,519 716,519 790,445 790,398 v1(909.5,278.5)
  Bottom Layer w20: v1(796,-479) 796,-449 1018,-227 1018,170 v1(909.5,278.5)
D7: R20.1 U3.13 | length 155.3
  Top Layer w10: U3.13@474.21,449.8 527.8,449.8 558,480 R20.1@617.01,480
D8: R21.1 U3.12 | length 123.1
  Top Layer w10: U3.12@499.8,424.21 567.79,424.21 582,410 R21.1@617.01,410
D9: R22.1 U3.11 | length 152.7
  Top Layer w10: U3.11@499.8,404.53 539.47,404.53 579,365 579,350 589,340 R22.1@617.01,340
EN_LP: J6.6 U3.5 | length 1243
  Top Layer w8: U3.5@454.53,300.2 454.53,263.47 485,233 511,233 640,104 961,104 1001,64 1001,-134 1063.25,-196.25 J6.6@1063.25,-487.41
GND: BT1.2 C1.2 C2.2 C3.2 C4.2 C5.2 C6.2 C7.2 C8.2 C9.2 C10.2 C11.2 C12.1 C13.1 C16.2 C17.2 C18.2 C19.2 C20.2 D3.2 D4.2 D7.2 D10.2 D13.2 D16.2 D19.2 J1.1 J3.6 J4.2 J5.2 J7.1 R2.2 R5.1 R6.1 R8.1 R10.1 R11.1 R12.1 R18.1 R19.1 R26.1 U1.1 U1.6 U1.15 U1.16 U1.17 U1.21 U2.5 U3.4 U3.20 U3.21 U3.25 U4.11 U5.2 U5.3 U5.7 U6.2 U7.1 | length 3246.2
  Top Layer w8: U1.1@-339.96,164.37 -314.37,164.37 U1.21@-275,125 ; U1.6@-314.37,60.04 -314.37,85.63 U1.21@-275,125 ; U1.17@-255.32,189.96 U1.21@-255.32,144.68 ; U1.16@-235.63,189.96 -215.96,189.96 -210.04,184.04 U1.15@-210.04,164.37 -235.63,164.37 U1.21@-255.32,144.68 ; v2(-5,730) -5,742 8.79,755.79 U5.3@32.4,755.79 ; U5.2@32.4,730 55,730 64.8,739.8 64.8,755.79 ; U1.21@-275,125 U1.21@-255.32,144.68
  Top Layer w10: U3.21@350.2,384.84 405.31,384.84 U3.25@410.24,389.76 ; U3.20@350.2,404.53 395.47,404.53 U3.25@410.24,389.76 ; U3.4@434.84,300.2 434.84,365.16 v2(425,375) U3.25@410.24,389.76
  Top Layer w15: v1(-693,-755) -668,-755.02 U6.2@-637.27,-755.09 ; U2.5@-618.86,-368.39 -526.89,-368.39 C10.2@-525,-366.5 ; U7.1@633.02,714.37 660.63,714.37 685.04,689.96 C20.2@722.5,689.96
  Top Layer w20: R10.1@-939.05,-253.3 v1(-939.05,-205.8) ; v1(-865.2,-213.74) R5.1@-817.69,-213.74 ; R26.1@-815,-738.5 R26.1@-815,-737.01 v1(-815,-695) ; C2.2@-760.81,555.6 v1(-735,600) ; v1(-727.91,-145.8) C4.2@-680.41,-145.8 ; v1(-710,-499.06) R11.1@-710,-451.56 ; C3.2@-700.81,520.6 v1(-675,565) ; v1(-579,-10) C5.2@-531.5,-10 ; v1(-579,55) R2.2@-531.5,55 ; C10.2@-525,-366.5 v1(-477.5,-366.5) ; v1(-437.5,-136.57) R6.1@-390,-136.57 R8.1@-320,-136.57 ; C6.2@-395,381.5 v1(-395,425) ; C7.2@-325,381.5 v1(-325,424) ; C8.2@-235.63,446.93 v1(-235.63,494.43) ; v1(-110,-655) D19.2@-35.04,-655 ; C9.2@-110,444.96 v1(-110,492.46) ; R12.1@-18.5,107.24 v1(29,107.24) ; 64.8,755.79 75.51,766.5 v1(108,766.5) ; v1(186.63,457.97) C11.2@234.14,457.97 ; v1(432.26,-135) R19.1@479.76,-135 ; v1(500.18,130.23) C17.2@500.18,177.73 ; v1(590,689) 590,643.01 C19.2@590.26,642.75 ; C13.1@651.54,-297.94 v1(651.54,-242.54) ; R18.1@680,270 v1(727.5,270) ; C20.2@722.5,689.96 v1(770.01,689.96) ; C12.1@938.46,-25 v1(938.46,30.4)
  Top Layer w25: v1(-1154.53,-127.53) D3.2@-1154.53,-59.06 ; D3.2@-1154.53,59.06 v1(-1154.53,127.53) ; D3.2@-1095.47,59.06 v1(-1095.47,127.53) ; D16.2@-592.03,-1025.42 v1(-517,-1072) ; v1(439,-1019) D13.2@496.12,-985.6 ; v1(468.53,-1070.14) D13.2@525.65,-1036.74 ; v1(471,1066) D7.2@528.62,1033.71 ; D7.2@601.38,923.51 v1(659,891.22) ; D13.2@627.94,-977.69 v1(685.06,-944.28) ; D7.2@630.91,974.65 v1(688.53,942.36)
  Top Layer w30: D4.2@-593.16,1033 v1(-504,1085) ; D10.2@1193.05,0 v1(1193.05,88.05)
  Bottom Layer w20: C18.2@-548.68,-792.5 v1(-490.5,-792.5) ; C16.2@65,766.5 v1@107,766.5
  other v2: -275,94.49 -305.51,125 -244.49,125 -275,155.51 425,333.66 383.66,375 466.34,375 425,416.34
  other v3: 680,-182.56 660.32,-155 699.68,-155 680,-127.44
INT_OPT: J7.2 R24.1 U5.5 | length 495.8
  Top Layer w10: v1(-114.5,766.5) -78.01,730 U5.5@-42.4,730
  Bottom Layer w20: J7.2@-335,588.3 -178.7,588.3 -133,634 -133,748 v1(-114.5,766.5) R24.1@-67,766.5
NetC1_1: C1.1 C4.1 R3.2 R4.2 U2.8 | length 769.8
  Top Layer w20: R3.2@-1052.72,-304.25 -1047.87,-299.4 -1047.87,-212.56 -920.31,-85 C1.1@-810,-85 -640,-85 -617.42,-107.58 C4.1@-617.42,-145.8 -618.2,-146.59 R4.2@-618.2,-213.74 -618.2,-289.82 U2.8@-618.86,-290.47
NetC5_1: C5.1 U1.4 | length 230.2
  Top Layer w8: C5.1@-468.5,-10 -427,-10 -417,0 -417,92 -403.68,105.32 U1.4@-339.96,105.32
NetC6_1: C6.1 C7.1 Q1.3 U1.19 | length 377.3
  Top Layer w8: -315,233.58 -294.69,213.27 U1.19@-294.69,189.96
  Top Layer w20: Q1.3@-494.88,416.77 -471.11,393 -453,393 -437,377 -437,333.24 -422.27,318.5 C6.1@-395,318.5 C7.1@-325,318.5 -325,243.58 -315,233.58
NetC11_1: C11.1 U3.22 | length 128.4
  Top Layer w8: C11.1@234.14,394.98 280.02,394.98 309.84,365.16 U3.22@350.2,365.16
NetC13_2: C13.2 D2.1 D5.1 D6.1 U4.7 | length 1337.8
  Top Layer w10: C13.2@718.46,-297.94 C13.2@725,-297.94 762.46,-297.94 v1(783.7,-276.7) ; U4.7@735.12,-174.69 758.39,-174.69 v1(783.7,-200)
  Top Layer w20: D6.1@23.59,-389.06 92.06,-389.06 ; D5.1@190.29,-437.78 180.51,-428 131,-428 92.06,-389.06 ; v1(413,-376) 413,-342 322,-251 205,-251 158,-298 158,-323.11 92.06,-389.06 ; v1(783.7,-276.7) 796.94,-276.7 816.69,-296.45 D2.1@816.69,-320
  Bottom Layer w20: v1(413,-376) 445,-344 716.4,-344 v1(783.7,-276.7) v1(783.7,-200)
NetC14_1: C14.1 U3.2 | length 134.9
  Top Layer w8: C14.1@365.18,177.8 365.18,230.18 395.47,260.47 U3.2@395.47,300.2
NetC14_2: C14.2 U3.24 | length 167.9
  Top Layer w8: C14.2@302.18,177.8 302.18,252.18 350.2,300.2 U3.24@350.2,325.79
NetC15_1: C15.1 U3.1 | length 193.1
  Top Layer w8: C15.1@234.14,263.49 268.49,263.49 v1(295,290) ; v1(355,260) 375.79,280.79 U3.1@375.79,300.2
  Bottom Layer w8: v1(295,290) 325,290 v1(355,260)
NetC15_2: C15.2 U3.23 | length 123.9
  Top Layer w8: C15.2@234.14,326.48 286.48,326.48 305.47,345.47 U3.23@350.2,345.47
NetC19_1: C19.1 R28.1 U7.7 | length 257.5
  Top Layer w10: R28.1@375.26,707.75 417.75,707.75 449.96,739.96 U7.7@477.5,739.96 510.04,739.96 527.27,722.73 C19.1@527.27,642.75 C19.1@527.27,637.75
NetD1_2: D1.2 J1.2 R30.1
NetD2_2: D2.2 L2.2 U4.6 | length 277.3
  Top Layer w10: U4.6@735.12,-194.37 735.12,-224.12 748,-237
  Top Layer w20: 748,-237 888,-237 903.31,-252.31 D2.2@903.31,-320
NetD5_2: D5.2 D8.1 | length 613.6
  Top Layer w20: D5.2@259.71,-342.22 316.49,-399 385,-399 501.5,-515.5 501.5,-596.5 461.08,-636.92 461.08,-682.25 D8.1@418.68,-790.82
NetD6_2: D6.2 D9.1 | length 681.1
  Top Layer w20: D6.2@23.59,-270.94 90,-270.94 103,-283.94 v1(103,-324) ; v1(103,-460) 157,-514 239,-514 298,-455 391,-455 398,-462 404.31,-480.55 422.29,-533.4 D9.1@422.33,-533.5
  Bottom Layer w20: v1(103,-460) v1(103,-324)
NetD8_2: D8.2 D11.1 | length 418.4
  Top Layer w20: D11.1@23.59,-940.94 23.59,-852.41 80,-796 273,-796 312.25,-756.75 D8.2@313.84,-756.75
NetD9_2: D9.2 D12.1 | length 424
  Top Layer w20: v1(149,-843) D12.1@185.29,-887.22 ; v1(199,-743) 199,-623 226,-596 D9.2@310,-570
  Bottom Layer w20: v1(149,-843) 199,-793 v1(199,-743)
NetD11_2: D11.2 D14.1 | length 663.5
  Top Layer w20: D14.1@-386.16,-798.25 D14.1@-386.11,-798.42 ; D14.1@-378.68,-795.82 -346,-870 -280,-870 -238,-828 -110,-828 -67,-871 -67,-1041 -48.94,-1059.06 D11.2@23.59,-1059.06
NetD12_2: D12.2 D15.1 | length 607.9
  Top Layer w20: D15.1@-230.69,-1005 -217,-1005 -112,-1110 163,-1110 191,-1082 191,-1037 245.22,-982.78 D12.2@254.71,-982.78
NetD14_2: D14.2 D17.1 | length 416.8
  Top Layer w20: D14.2@-273.84,-761.75 -268.08,-756 -192,-756 -168,-732 -168,-465.49 D17.1@-145.29,-442.78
